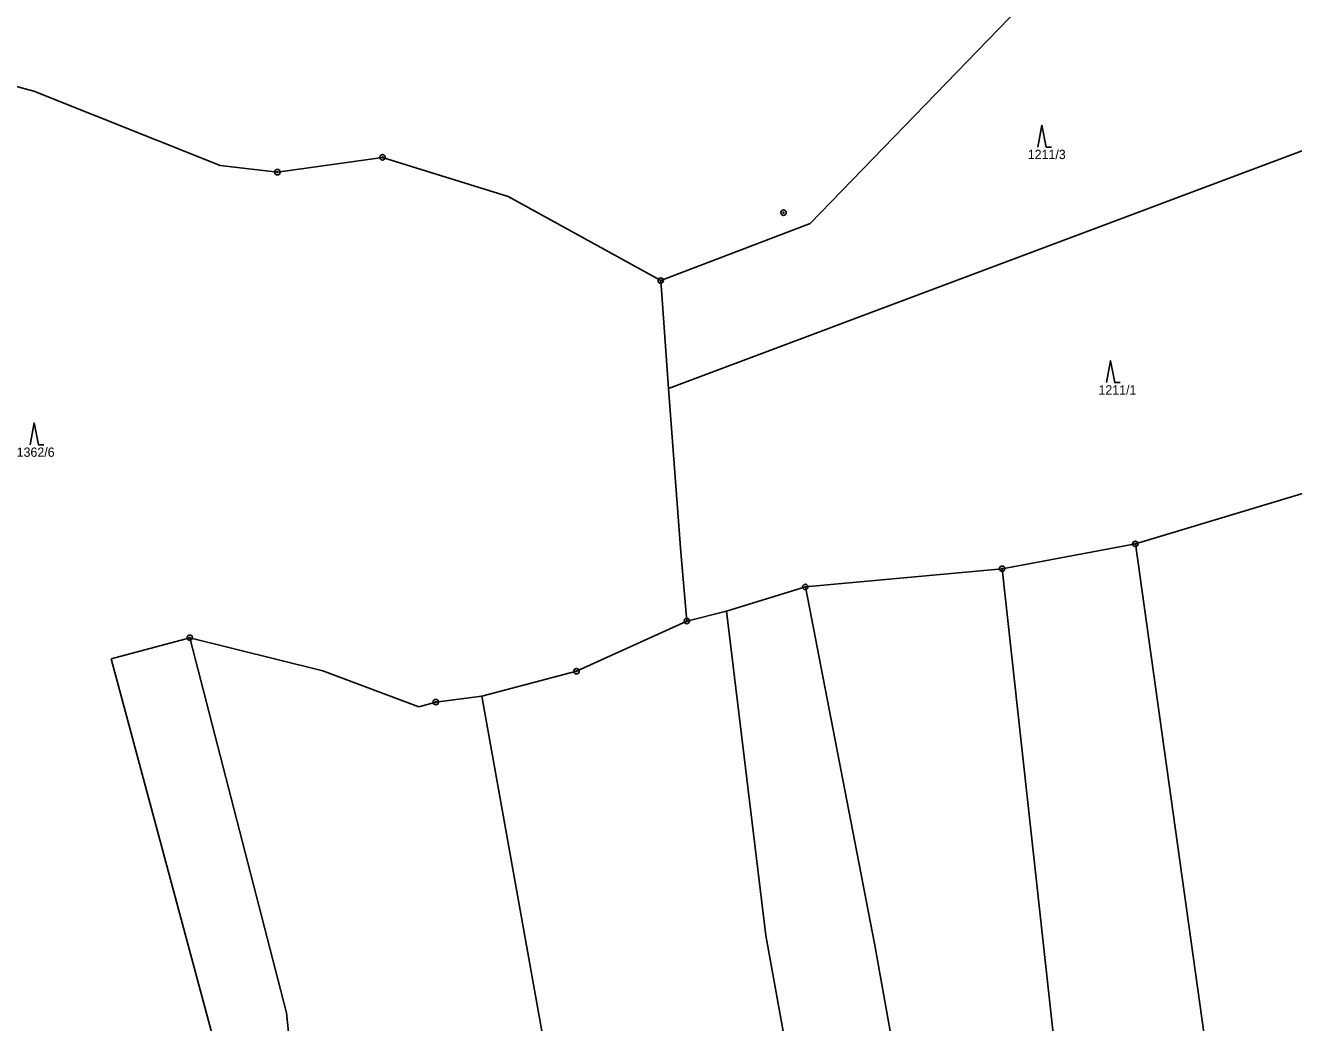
# Model space of a CAD drawing. Extents: x -763205 to -760228, y -1155311 to -1152844.
# Drawn here: x -760753.2 to -760520.7, y -1154488.2 to -1154305.4 of the extents above; entities that cross this region are included whole.
import ezdxf

# ---------------------------------------------------------------- set-up
doc = ezdxf.new("R2010")
doc.units = 0
for name, color, linetype in [('Vrstva 1', 7, 'Continuous'), ('Vrstva 18', 7, 'Continuous'), ('Vrstva 24', 7, 'Continuous'), ('Vrstva 25', 7, 'Continuous'), ('Vrstva 6', 7, 'Continuous')]:
    doc.layers.add(name, color=color, linetype=linetype)

msp = doc.modelspace()

# ---------------------------------------------------------------- linework, layer by layer
at = {"layer": 'Vrstva 1'}
for p, q in [((-760574.12, -1154405.02), (-760549.69, -1154400.46)), ((-760610.21, -1154408.36), (-760574.12, -1154405.02)), ((-760652.16, -1154423.81), (-760631.95, -1154414.61))]:
    msp.add_line(p, q, dxfattribs=at)
at = {"layer": 'Vrstva 24'}
for centre, radius in [((-760687.74, -1154329.6), 0.5), ((-760687.74, -1154329.6), 0.1), ((-760707.02, -1154332.31), 0.5), ((-760707.02, -1154332.31), 0.1), ((-760614.21, -1154339.73), 0.5), ((-760614.21, -1154339.73), 0.1), ((-760636.73, -1154352.19), 0.5), ((-760636.73, -1154352.19), 0.1), ((-760549.69, -1154400.46), 0.5), ((-760549.69, -1154400.46), 0.1), ((-760574.12, -1154405.02), 0.5), ((-760574.12, -1154405.02), 0.1), ((-760610.21, -1154408.36), 0.5), ((-760610.21, -1154408.36), 0.1), ((-760631.95, -1154414.61), 0.5), ((-760631.95, -1154414.61), 0.1), ((-760723.1, -1154417.67), 0.5), ((-760723.1, -1154417.67), 0.1), ((-760652.16, -1154423.81), 0.5), ((-760652.16, -1154423.81), 0.1), ((-760677.98, -1154429.48), 0.5), ((-760677.98, -1154429.48), 0.1)]:
    msp.add_circle(centre, radius, dxfattribs=at)
at = {"layer": 'Vrstva 25'}
for points in [[(-760567.55, -1154327.71), (-760566.85, -1154323.71), (-760566.05, -1154327.71), (-760565.05, -1154327.71)], [(-760554.98, -1154370.88), (-760554.28, -1154366.88), (-760553.48, -1154370.88), (-760552.48, -1154370.88)], [(-760752.36, -1154382.3), (-760751.66, -1154378.3), (-760750.86, -1154382.3), (-760749.86, -1154382.3)]]:
    msp.add_lwpolyline(points, dxfattribs=at)
at = {"layer": 'Vrstva 6'}
for p, q in [((-760609.35, -1154341.75), (-760548.38, -1154278.77)), ((-760810.09, -1154301.76), (-760751.67, -1154317.46)), ((-760751.67, -1154317.46), (-760717.5, -1154331.1)), ((-760635.29, -1154372), (-760502.34, -1154322.12)), ((-760707.02, -1154332.31), (-760687.74, -1154329.6)), ((-760687.74, -1154329.6), (-760664.69, -1154336.79)), ((-760717.5, -1154331.1), (-760707.02, -1154332.31)), ((-760664.69, -1154336.79), (-760636.73, -1154352.19)), ((-760636.73, -1154352.19), (-760609.35, -1154341.75)), ((-760636.73, -1154352.19), (-760635.29, -1154372)), ((-760635.29, -1154372), (-760633.03, -1154401.96)), ((-760549.69, -1154400.46), (-760513.54, -1154389.56)), ((-760549.69, -1154400.46), (-760534.39, -1154509.56)), ((-760633.03, -1154401.96), (-760631.95, -1154414.61)), ((-760574.12, -1154405.02), (-760562.13, -1154514.13)), ((-760624.66, -1154412.78), (-760610.21, -1154408.36)), ((-760610.21, -1154408.36), (-760597.51, -1154473.75)), ((-760631.95, -1154414.61), (-760624.66, -1154412.78)), ((-760624.66, -1154412.78), (-760617.44, -1154472.29)), ((-760737.54, -1154421.53), (-760723.1, -1154417.67)), ((-760723.1, -1154417.67), (-760698.71, -1154423.73)), ((-760723.1, -1154417.67), (-760705.34, -1154486.45)), ((-760737.54, -1154421.53), (-760718.8, -1154491.08)), ((-760698.71, -1154423.73), (-760681.12, -1154430.33)), ((-760669.51, -1154428.39), (-760652.16, -1154423.81)), ((-760677.98, -1154429.48), (-760669.51, -1154428.39)), ((-760669.51, -1154428.39), (-760655.93, -1154504.3)), ((-760681.12, -1154430.33), (-760677.98, -1154429.48)), ((-760617.44, -1154472.29), (-760601.32, -1154561.82)), ((-760597.51, -1154473.75), (-760583.48, -1154552.72)), ((-760705.34, -1154486.45), (-760691.8, -1154619.78))]:
    msp.add_line(p, q, dxfattribs=at)

# ---------------------------------------------------------------- texts
at = {"layer": 'Vrstva 18'}
for s, p in [('1211/3', (-760569.417, -1154329.91)), ('1211/1', (-760556.457, -1154373.08)), ('1362/6', (-760754.837, -1154384.5))]:
    msp.add_text(s, height=1.7, dxfattribs=at).set_placement(p)

doc.saveas('drawing.dxf')
